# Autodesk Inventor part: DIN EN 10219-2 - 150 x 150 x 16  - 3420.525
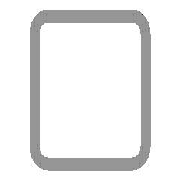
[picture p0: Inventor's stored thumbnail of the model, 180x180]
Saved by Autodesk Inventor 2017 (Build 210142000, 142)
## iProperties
IsCustomPart: 1
_CCFamilyMember: 76
_CCFamilyDisplayName: DIN EN 10219-2 (Square Hollow Section - Cold Formed) - Cold formed welded structural hollow sections of non-alloy and fine grain structural steel
_FrameMemberDoc: Frame Member File
_Version: 15.0.0
_GetPNFromCC: 1
Created: 2016-02
Part Number: DIN EN 10219-2 - 150 x 150 x 16  - 3420.525
Material: Steel, Mild
Description: Cold formed welded structural hollow sections of non-alloy and fine grain structural steel
Document SubType Name: Modeling
Standard: DIN
Designer: iusti
Standard Revision: 2006-07
Standards Organization: DIN
Language: en-US
Size Designation: 150 x 150 x 16
Categories: <MemberInstance><Categories><Category DisplayName="Structural Shapes" InternalName="089c4875-fa83-4c05-b084-43b9cc11f5ed" Mnemonic="GRDR"><CategoryParameter Dis
Stock Number: 150 x 150 x 16
Density: 7.85 g/cm^3
Appearance: Semi-Polished
Mass: 187715 g
Surface Area: 30177.9 cm^2
Volume: 23912.8 cm^3
G_L: 3420.525 mm
G_W: 150.000 mm
G_H: 150.000 mm
+A2FA36FB-A031-4659-8CB0-A5A84C4F6311+CUTDETAIL1: Cut
+96BC65A8-7812-439C-A6F9-D3AF540F1DD0+CUTDETAIL2: Cut
Author: iusti
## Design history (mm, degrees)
node "Start plane"
node "End plane"
sketch "Sketch"
  geometry: L1 (-75, -27)-(-75, 27); L2 (-27, 75)-(27, 75); L3 (75, 27)-(75, -27); L4 (27, -75)-(-27, -75); L5 (-27, 59)-(27, 59); L6 (59, 27)-(59, -27); L7 (27, -59)-(-27, -59); L8 (-59, -27)-(-59, 27); L9 (0, 118.918)-(0, -118.918) reference; L10 (-118.918, 0)-(118.918, 0) reference; A1 r 48 centre (-27, -27) between (-75, -27) and (-27, -75); A2 r 48 centre (-27, 27) between (-27, 75) and (-75, 27); A3 r 48 centre (27, 27) between (75, 27) and (27, 75); A4 r 48 centre (27, -27) between (27, -75) and (75, -27); A5 r 32 centre (-27, 27) between (-27, 59) and (-59, 27); A6 r 32 centre (27, 27) between (59, 27) and (27, 59); A7 r 32 centre (27, -27) between (27, -59) and (59, -27); A8 r 32 centre (-27, -27) between (-59, -27) and (-27, -59)
  constraints: 16 end point, 16 point on circle, 8 centre point, 8 tangent, 4 parallel, 3 equal radius, 2 perpendicular, 7 other
  dimensions: "d7" = 48 radius of A1 (= G_IR); "d10" = 150 distance between parallel lines of L2 L4 (= G_H); "d11" = 150 distance between parallel lines of L1 L3 (= G_W); "d12" = 16 distance between parallel lines of L3 L6 (= G_T); "d15" = 75 distance between parallel lines of L2 L10 (= 0.5 x d10); "d16" = 75 distance between parallel lines of L9 L3 (= 0.5 x d11)
extrude "Body" new body sketch "Sketch" stored distance "d3" = 3420.52498 (= G_L); taper "d4" = 0 deg
node "Driven Length"
  sketch "Sketch3"
    geometry: L1 (0, 0)-(10, 0) reference
    constraints: 2 end point, 1 horizontal
  workplane "Work Plane3"
  sketch "Sketch4"
    geometry: L1 (-2, 14.036)-(12, 14.036) reference; L2 (-2, 3434.561)-(12, 3434.561) reference
    dimensions: "d18" = 3420.52498 distance between parallel lines of L1 L2 (derived)
workplane "Work Plane4"
split "Split1"
workplane "Work Plane5"
split "Split2"
body "Solid1"
other parameters: "G_W" = 150 [user parameter; used in 1 equation term], "G_H" = 150 [user parameter; used in 1 equation term], "G_T" = 16 [user parameter; used in 1 equation term], "G_IR" = 48 [user parameter; used in 1 equation term], "G_L" = 3420.52498 (= d18) [user parameter; used in 1 equation term], "G_OFFSET_START" = -14.0359 [user parameter; used in 1 equation term], "G_OFFSET_END" = -22.05576 [user parameter; used in 1 equation term], "d13" = 14.0359 (= -G_OFFSET_START), "d14" = 3434.56088 (= G_OFFSET_END + B_L), "B_L" = 3456.61664 [user parameter; used in 1 equation term], "d17" = 90 deg
